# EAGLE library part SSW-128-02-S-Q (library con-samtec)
THROUGH-HOLE .025" SQ POST SOCKET Source: Samtec SSW.pdf
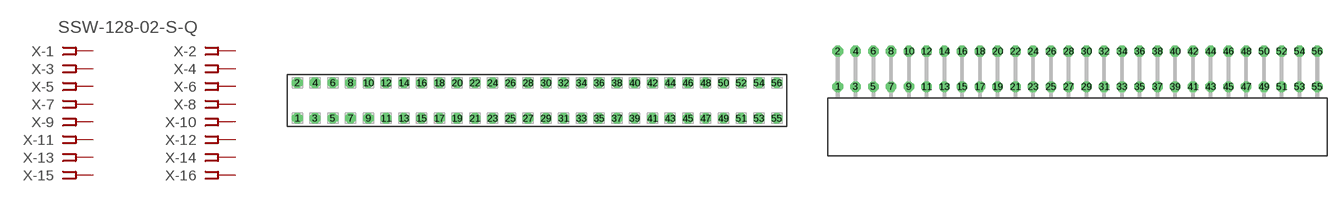
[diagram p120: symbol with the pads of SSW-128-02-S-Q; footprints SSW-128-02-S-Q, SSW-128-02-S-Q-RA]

Designator prefix X; gates -1=FPINV -2=FPIN -3=FPIN -4=FPIN -5=FPIN -6=FPIN -7=FPIN -8=FPIN -9=FPIN -10=FPIN -11=FPIN -12=FPIN -13=FPIN -14=FPIN -15=FPIN -16=FPIN -17=FPIN -18=FPIN -19=FPIN -20=FPIN -21=FPIN -22=FPIN -23=FPIN -24=FPIN -25=FPIN -26=FPIN -27=FPIN -28=FPIN -29=FPIN -30=FPIN -31=FPIN -32=FPIN -33=FPIN -34=FPIN -35=FPIN -36=FPIN -37=FPIN -38=FPIN -39=FPIN -40=FPIN -41=FPIN -42=FPIN -43=FPIN -44=FPIN -45=FPIN -46=FPIN -47=FPIN -48=FPIN -49=FPIN -50=FPIN -51=FPIN -52=FPIN -53=FPIN -54=FPIN -55=FPIN -56=FPIN

## SSW-128-02-S-Q (OC_FARNELL: unknown; OC_NEWARK: unknown)  [SSW-128-02-S-Q]
1  -1:1  pas
2  -2:1  pas
3  -3:1  pas
4  -4:1  pas
5  -5:1  pas
6  -6:1  pas
7  -7:1  pas
8  -8:1  pas
9  -9:1  pas
10  -10:1  pas
11  -11:1  pas
12  -12:1  pas
13  -13:1  pas
14  -14:1  pas
15  -15:1  pas
16  -16:1  pas
17  -17:1  pas
18  -18:1  pas
19  -19:1  pas
20  -20:1  pas
21  -21:1  pas
22  -22:1  pas
23  -23:1  pas
24  -24:1  pas
25  -25:1  pas
26  -26:1  pas
27  -27:1  pas
28  -28:1  pas
29  -29:1  pas
30  -30:1  pas
31  -31:1  pas
32  -32:1  pas
33  -33:1  pas
34  -34:1  pas
35  -35:1  pas
36  -36:1  pas
37  -37:1  pas
38  -38:1  pas
39  -39:1  pas
40  -40:1  pas
41  -41:1  pas
42  -42:1  pas
43  -43:1  pas
44  -44:1  pas
45  -45:1  pas
46  -46:1  pas
47  -47:1  pas
48  -48:1  pas
49  -49:1  pas
50  -50:1  pas
51  -51:1  pas
52  -52:1  pas
53  -53:1  pas
54  -54:1  pas
55  -55:1  pas
56  -56:1  pas

## SSW-128-02-S-QRA (OC_FARNELL: unknown; OC_NEWARK: unknown)  [SSW-128-02-S-Q-RA]
Pads as for SSW-128-02-S-Q

## Footprint SSW-128-02-S-Q (pad centres in mm)
THROUGH-HOLE .025" SQ POST SOCKET Source: Samtec SSW.pdf
drill 1 pad 1.5 octagon: 1 -34.29,-2.54; 2 -34.29,2.54; 3 -31.75,-2.54; 4 -31.75,2.54; 5 -29.21,-2.54; 6 -29.21,2.54; 7 -26.67,-2.54; 8 -26.67,2.54; 9 -24.13,-2.54; 10 -24.13,2.54; 11 -21.59,-2.54; 12 -21.59,2.54; 13 -19.05,-2.54; 14 -19.05,2.54; 15 -16.51,-2.54; 16 -16.51,2.54; 17 -13.97,-2.54; 18 -13.97,2.54; 19 -11.43,-2.54; 20 -11.43,2.54; 21 -8.89,-2.54; 22 -8.89,2.54; 23 -6.35,-2.54; 24 -6.35,2.54; 25 -3.81,-2.54; 26 -3.81,2.54; 27 -1.27,-2.54; 28 -1.27,2.54; 29 1.27,-2.54; 30 1.27,2.54; 31 3.81,-2.54; 32 3.81,2.54; 33 6.35,-2.54; 34 6.35,2.54; 35 8.89,-2.54; 36 8.89,2.54; 37 11.43,-2.54; 38 11.43,2.54; 39 13.97,-2.54; 40 13.97,2.54; 41 16.51,-2.54; 42 16.51,2.54; 43 19.05,-2.54; 44 19.05,2.54; 45 21.59,-2.54; 46 21.59,2.54; 47 24.13,-2.54; 48 24.13,2.54; 49 26.67,-2.54; 50 26.67,2.54; 51 29.21,-2.54; 52 29.21,2.54; 53 31.75,-2.54; 54 31.75,2.54; 55 34.29,-2.54; 56 34.29,2.54

## Footprint SSW-128-02-S-Q-RA (pad centres in mm)
THROUGH-HOLE .025" SQ POST SOCKET Source: Samtec SSW.pdf
drill 1 pad 1.5 octagon: 1 -34.29,1.524; 2 -34.29,6.604; 3 -31.75,1.524; 4 -31.75,6.604; 5 -29.21,1.524; 6 -29.21,6.604; 7 -26.67,1.524; 8 -26.67,6.604; 9 -24.13,1.524; 10 -24.13,6.604; 11 -21.59,1.524; 12 -21.59,6.604; 13 -19.05,1.524; 14 -19.05,6.604; 15 -16.51,1.524; 16 -16.51,6.604; 17 -13.97,1.524; 18 -13.97,6.604; 19 -11.43,1.524; 20 -11.43,6.604; 21 -8.89,1.524; 22 -8.89,6.604; 23 -6.35,1.524; 24 -6.35,6.604; 25 -3.81,1.524; 26 -3.81,6.604; 27 -1.27,1.524; 28 -1.27,6.604; 29 1.27,1.524; 30 1.27,6.604; 31 3.81,1.524; 32 3.81,6.604; 33 6.35,1.524; 34 6.35,6.604; 35 8.89,1.524; 36 8.89,6.604; 37 11.43,1.524; 38 11.43,6.604; 39 13.97,1.524; 40 13.97,6.604; 41 16.51,1.524; 42 16.51,6.604; 43 19.05,1.524; 44 19.05,6.604; 45 21.59,1.524; 46 21.59,6.604; 47 24.13,1.524; 48 24.13,6.604; 49 26.67,1.524; 50 26.67,6.604; 51 29.21,1.524; 52 29.21,6.604; 53 31.75,1.524; 54 31.75,6.604; 55 34.29,1.524; 56 34.29,6.604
